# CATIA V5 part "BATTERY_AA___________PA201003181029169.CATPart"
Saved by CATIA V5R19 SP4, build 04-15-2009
Part number: BATTERY_AA___________PA201003181029169
Bounding box of the stored display mesh (mm): x -7 to 7, y -7 to 7, z 0 to 51
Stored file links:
  E:\CadInnWork\InWork\BATTERY_AA___________PA201003181029169.CATPart
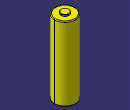
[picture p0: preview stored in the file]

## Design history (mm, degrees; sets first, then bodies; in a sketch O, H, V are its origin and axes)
Parameters
  Update = false
  PDM_version = "A"
  PDM_iteration = 1
  PDM_owner = "moren                    "
  PDM_comment = ""
  PDM_partnumber = "PA002170EA6A57201003181029160009"
Body1 (main body)
  Sketch1 on xy-plane, origin (0, 0, 0), H (1, 0, 0), V (0, 1, 0)
    circle A1 centre (0, 0) radius 7
    radius A1 = 7
  Pad1: profile Sketch1, direction (0, 0, 1), length 50
  Sketch2 on end face of Pad1, origin (0, 0, 50), H (1, 0, 0), V (0, 1, 0)
    circle A1 centre (0, 0) radius 2.75
    radius A1 = 2.75
  Pad2: profile Sketch2, direction (0, 0, 1), length 1
  Fillet1: radius 0.5, on edge [face of Pad1 from Sketch1.A1 | end face of Pad1]; edge [start face of Pad1 | face of Pad1 from Sketch1.A1]
  Fillet2: radius 0.2, on edge [face of Pad2 from Sketch2.A1 | end face of Pad2]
